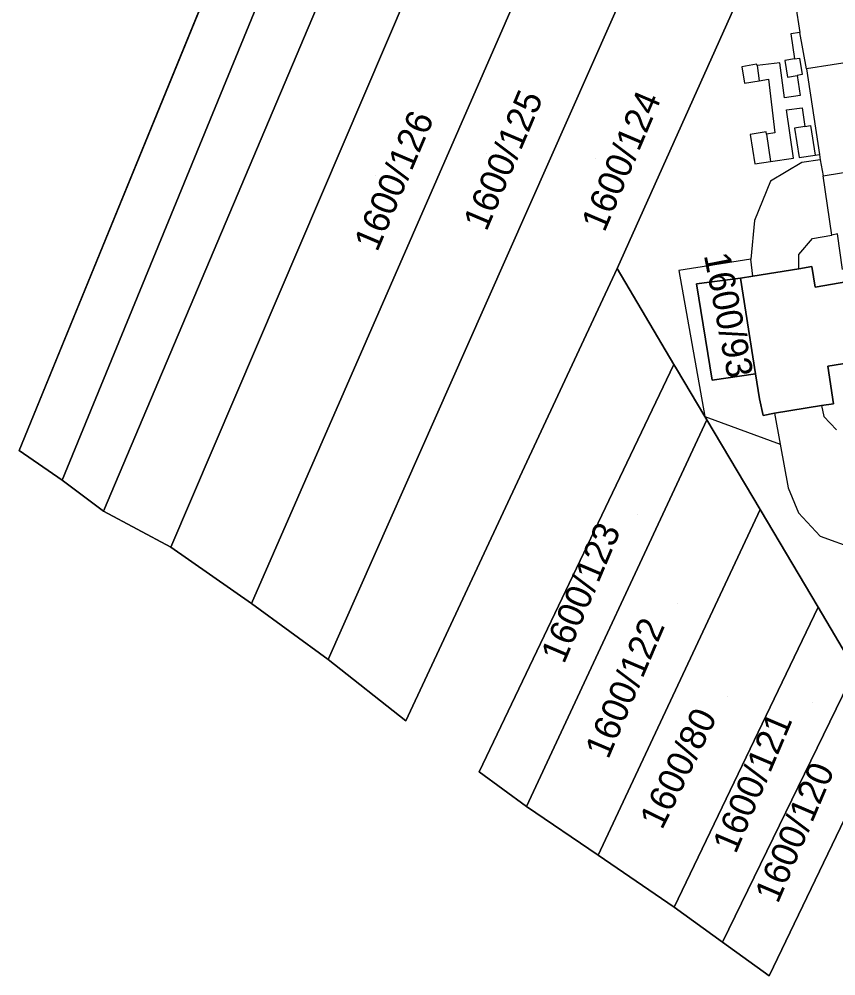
# Model space of a CAD drawing. Extents: x -262715 to -259381, y -1237238 to -1231182.
# Drawn here: x -261772.8 to -261710.5, y -1236430.9 to -1236357.8 of the extents above; entities that cross this region are included whole.
import ezdxf

# ---------------------------------------------------------------- set-up
doc = ezdxf.new("R2010")
doc.units = 0
for name, color, linetype in [('body_kn', 7, 'Continuous'), ('kladpar_druhypozemkov', 7, 'Continuous'), ('kladpar_hranice', 7, 'Continuous'), ('kladpar_parcelnecisla', 7, 'Continuous'), ('kladpar_plochy', 7, 'Continuous'), ('zappar_hrandruhpozemk', 7, 'Continuous')]:
    doc.layers.add(name, color=color, linetype=linetype)

msp = doc.modelspace()

# ---------------------------------------------------------------- linework, layer by layer
at = {"layer": 'body_kn'}
for p, q in [((-261713.93, -1236358.96), (-261713.93, -1236358.96)), ((-261713.23, -1236358.87), (-261713.23, -1236358.87)), ((-261717.68, -1236361.47), (-261717.68, -1236361.47)), ((-261716.56, -1236361.28), (-261716.56, -1236361.28)), ((-261716.51, -1236361.37), (-261716.51, -1236361.37)), ((-261716.51, -1236361.37), (-261716.51, -1236361.37)), ((-261714.76, -1236361.18), (-261714.76, -1236361.18)), ((-261714.39, -1236361), (-261714.39, -1236361)), ((-261713.64, -1236360.86), (-261713.64, -1236360.86)), ((-261713.27, -1236360.81), (-261713.27, -1236360.81)), ((-261713.45, -1236362.13), (-261713.45, -1236362.13)), ((-261713.06, -1236362.07), (-261713.06, -1236362.07)), ((-261712.74, -1236361.64), (-261712.74, -1236361.64)), ((-261712.74, -1236361.64), (-261712.74, -1236361.64)), ((-261717.47, -1236362.73), (-261717.47, -1236362.73)), ((-261716.35, -1236362.54), (-261716.35, -1236362.54)), ((-261715.64, -1236362.42), (-261715.64, -1236362.42)), ((-261714.18, -1236362.26), (-261714.18, -1236362.26)), ((-261713.21, -1236363.67), (-261713.21, -1236363.67)), ((-261714.41, -1236363.84), (-261714.41, -1236363.84)), ((-261714.27, -1236364.77), (-261714.27, -1236364.77)), ((-261713.07, -1236364.6), (-261713.07, -1236364.6)), ((-261715.82, -1236366.45), (-261715.82, -1236366.45)), ((-261715.14, -1236366.51), (-261715.14, -1236366.51)), ((-261713.64, -1236366.16), (-261713.64, -1236366.16)), ((-261712.85, -1236366.04), (-261712.85, -1236366.04)), ((-261712.85, -1236366.04), (-261712.85, -1236366.04)), ((-261712.42, -1236365.97), (-261712.42, -1236365.97)), ((-261717.04, -1236366.64), (-261717.04, -1236366.64)), ((-261715.78, -1236366.61), (-261715.78, -1236366.61)), ((-261715.78, -1236366.61), (-261715.78, -1236366.61)), ((-261715.47, -1236368.7), (-261715.47, -1236368.7)), ((-261715.47, -1236368.7), (-261715.47, -1236368.7)), ((-261713.73, -1236368.44), (-261713.73, -1236368.44)), ((-261713.29, -1236368.41), (-261713.29, -1236368.41)), ((-261713.1, -1236368.79), (-261713.1, -1236368.79)), ((-261712.07, -1236368.22), (-261712.07, -1236368.22)), ((-261711.75, -1236368.18), (-261711.75, -1236368.18)), ((-261711.68, -1236368.59), (-261711.68, -1236368.59)), ((-261711.68, -1236368.59), (-261711.68, -1236368.59)), ((-261716.69, -1236368.89), (-261716.69, -1236368.89)), ((-261715.49, -1236370.21), (-261715.49, -1236370.21)), ((-261711.45, -1236369.79), (-261711.45, -1236369.79)), ((-261711.45, -1236369.79), (-261711.45, -1236369.79)), ((-261716.7, -1236373.22), (-261716.7, -1236373.22)), ((-261712.28, -1236374.58), (-261712.28, -1236374.58)), ((-261710.81, -1236374.33), (-261710.81, -1236374.33)), ((-261710.81, -1236374.33), (-261710.81, -1236374.33)), ((-261713.32, -1236375.81), (-261713.32, -1236375.81)), ((-261716.98, -1236376.17), (-261716.98, -1236376.17)), ((-261716.98, -1236376.17), (-261716.98, -1236376.17)), ((-261712.32, -1236376.72), (-261712.32, -1236376.72)), ((-261727.2, -1236376.88), (-261727.2, -1236376.88)), ((-261727.2, -1236376.88), (-261727.2, -1236376.88)), ((-261722.49, -1236377.03), (-261722.49, -1236377.03)), ((-261716.84, -1236377.47), (-261716.84, -1236377.47)), ((-261716.84, -1236377.47), (-261716.84, -1236377.47)), ((-261713.33, -1236376.89), (-261713.33, -1236376.89)), ((-261713.33, -1236376.89), (-261713.33, -1236376.89)), ((-261721.13, -1236378.05), (-261721.13, -1236378.05)), ((-261717.77, -1236377.6), (-261717.77, -1236377.6)), ((-261717.77, -1236377.6), (-261717.77, -1236377.6)), ((-261712.07, -1236378.3), (-261712.07, -1236378.3)), ((-261738.7, -1236382.89), (-261738.7, -1236382.89)), ((-261722.86, -1236384.19), (-261722.86, -1236384.19)), ((-261722.86, -1236384.19), (-261722.86, -1236384.19)), ((-261722.66, -1236384.52), (-261722.66, -1236384.52)), ((-261711.11, -1236384.33), (-261711.11, -1236384.33)), ((-261719.93, -1236385.39), (-261719.93, -1236385.39)), ((-261716.63, -1236384.9), (-261716.63, -1236384.9)), ((-261716.31, -1236386.81), (-261716.31, -1236386.81)), ((-261711.58, -1236387.34), (-261711.58, -1236387.34)), ((-261711.58, -1236387.34), (-261711.58, -1236387.34)), ((-261710.66, -1236387.19), (-261710.66, -1236387.19)), ((-261720.49, -1236388.17), (-261720.49, -1236388.17)), ((-261720.49, -1236388.17), (-261720.49, -1236388.17)), ((-261720.34, -1236388.42), (-261720.34, -1236388.42)), ((-261720.34, -1236388.42), (-261720.34, -1236388.42)), ((-261716.03, -1236388.08), (-261716.03, -1236388.08)), ((-261715.17, -1236387.91), (-261715.17, -1236387.91)), ((-261715.17, -1236387.91), (-261715.17, -1236387.91)), ((-261711.41, -1236388.18), (-261711.41, -1236388.18)), ((-261714.75, -1236390.29), (-261714.75, -1236390.29)), ((-261772.85, -1236390.76), (-261772.85, -1236390.76)), ((-261772.85, -1236390.76), (-261772.85, -1236390.76)), ((-261769.56, -1236393.02), (-261769.56, -1236393.02)), ((-261714.13, -1236393.6), (-261714.13, -1236393.6)), ((-261766.42, -1236395.39), (-261766.42, -1236395.39)), ((-261766.42, -1236395.39), (-261766.42, -1236395.39)), ((-261716.28, -1236395.26), (-261716.28, -1236395.26)), ((-261713.34, -1236395.53), (-261713.34, -1236395.53)), ((-261711.68, -1236397.29), (-261711.68, -1236397.29)), ((-261761.26, -1236398.13), (-261761.26, -1236398.13)), ((-261755.1, -1236402.44), (-261755.1, -1236402.44)), ((-261755.1, -1236402.44), (-261755.1, -1236402.44)), ((-261711.85, -1236402.73), (-261711.85, -1236402.73)), ((-261749.26, -1236406.71), (-261749.26, -1236406.71)), ((-261749.26, -1236406.71), (-261749.26, -1236406.71)), ((-261743.32, -1236411.39), (-261743.32, -1236411.39)), ((-261737.72, -1236415.3), (-261737.72, -1236415.3)), ((-261734.11, -1236417.94), (-261734.11, -1236417.94)), ((-261734.11, -1236417.94), (-261734.11, -1236417.94)), ((-261728.63, -1236421.65), (-261728.63, -1236421.65)), ((-261728.63, -1236421.65), (-261728.63, -1236421.65)), ((-261722.83, -1236425.61), (-261722.83, -1236425.61)), ((-261722.83, -1236425.61), (-261722.83, -1236425.61)), ((-261719.14, -1236428.29), (-261719.14, -1236428.29)), ((-261719.14, -1236428.29), (-261719.14, -1236428.29)), ((-261715.58, -1236430.86), (-261715.58, -1236430.86))]:
    msp.add_line(p, q, dxfattribs=at)
at = {"layer": 'kladpar_druhypozemkov'}
for p, q in [((-261737.17, -1236368.07), (-261737.17, -1236368.07)), ((-261728.81, -1236368.44), (-261728.81, -1236368.44)), ((-261745.66, -1236369.81), (-261745.66, -1236369.81)), ((-261717.79, -1236381.32), (-261717.79, -1236381.32)), ((-261725.64, -1236395.68), (-261725.64, -1236395.68)), ((-261722.61, -1236402.46), (-261722.61, -1236402.46)), ((-261718.76, -1236409.5), (-261718.76, -1236409.5)), ((-261712.31, -1236409.99), (-261712.31, -1236409.99))]:
    msp.add_line(p, q, dxfattribs=at)
at = {"layer": 'kladpar_hranice'}
for p, q in [((-261772.85, -1236390.76), (-261729.67, -1236285.32)), ((-261727.2, -1236376.88), (-261722.86, -1236384.19)), ((-261720.34, -1236388.42), (-261734.11, -1236417.94)), ((-261709.01, -1236407.5), (-261719.14, -1236428.29)), ((-261722.83, -1236425.61), (-261728.63, -1236421.65)), ((-261719.14, -1236428.29), (-261722.83, -1236425.61))]:
    msp.add_line(p, q, dxfattribs=at)
for points in [[(-261729.67, -1236285.32), (-261772.85, -1236390.76), (-261769.56, -1236393.02), (-261766.42, -1236395.39), (-261761.26, -1236398.13), (-261755.1, -1236402.44), (-261749.26, -1236406.71), (-261743.32, -1236411.39), (-261727.2, -1236376.88)], [(-261727.16, -1236289.77), (-261769.56, -1236393.02), (-261772.85, -1236390.76)], [(-261724.03, -1236295.33), (-261766.42, -1236395.39), (-261769.56, -1236393.02), (-261727.16, -1236289.77)], [(-261766.42, -1236395.39), (-261724.03, -1236295.33), (-261723.21, -1236296.78), (-261720.21, -1236302.16), (-261761.26, -1236398.13), (-261766.42, -1236395.39)], [(-261755.1, -1236402.44), (-261761.26, -1236398.13), (-261720.21, -1236302.16)], [(-261715.3, -1236310.95), (-261728.67, -1236341.94), (-261755.1, -1236402.44)], [(-261749.26, -1236406.71), (-261755.1, -1236402.44), (-261728.67, -1236341.94), (-261715.3, -1236310.95)], [(-261710.55, -1236319.47), (-261719.76, -1236340.21), (-261738.7, -1236382.89), (-261749.26, -1236406.71)], [(-261727.2, -1236376.88), (-261743.32, -1236411.39), (-261749.26, -1236406.71), (-261738.7, -1236382.89), (-261719.76, -1236340.21), (-261710.55, -1236319.47)], [(-261710.55, -1236319.47), (-261705.52, -1236328.61), (-261727.2, -1236376.88)], [(-261727.2, -1236376.88), (-261705.52, -1236328.61)], [(-261689.71, -1236357.2), (-261686.06, -1236363.77), (-261681.32, -1236372.31), (-261680.07, -1236374.57), (-261674.77, -1236384.12), (-261676.54, -1236387.86), (-261678.39, -1236391.77), (-261678.71, -1236392.44), (-261688.12, -1236412.33), (-261689.12, -1236412.13), (-261693.35, -1236411.27), (-261697.7, -1236410.38), (-261705.02, -1236408.89), (-261708.62, -1236408.16), (-261709.01, -1236407.5), (-261711.85, -1236402.73), (-261716.28, -1236395.26), (-261720.34, -1236388.42), (-261720.49, -1236388.17), (-261722.66, -1236384.52)], [(-261716.84, -1236377.47), (-261717.77, -1236377.6), (-261721.13, -1236378.05), (-261719.93, -1236385.39), (-261716.63, -1236384.9), (-261716.31, -1236386.81), (-261716.03, -1236388.08), (-261715.17, -1236387.91), (-261711.58, -1236387.34), (-261710.66, -1236387.19), (-261711.11, -1236384.33), (-261708.87, -1236383.97), (-261708.15, -1236388.1), (-261689.76, -1236385.07), (-261691.37, -1236374.95), (-261709.58, -1236377.86), (-261712.07, -1236378.3), (-261712.32, -1236376.72), (-261713.33, -1236376.89), (-261716.84, -1236377.47)], [(-261716.84, -1236377.47), (-261713.33, -1236376.89), (-261712.32, -1236376.72), (-261712.07, -1236378.3), (-261709.58, -1236377.86), (-261691.37, -1236374.95), (-261689.76, -1236385.07), (-261708.15, -1236388.1), (-261708.87, -1236383.97), (-261711.11, -1236384.33), (-261710.66, -1236387.19), (-261711.58, -1236387.34), (-261715.17, -1236387.91), (-261716.03, -1236388.08), (-261716.31, -1236386.81), (-261716.63, -1236384.9), (-261717.77, -1236377.6), (-261716.84, -1236377.47)], [(-261722.66, -1236384.52), (-261722.86, -1236384.19), (-261727.2, -1236376.88)], [(-261717.77, -1236377.6), (-261716.63, -1236384.9), (-261719.93, -1236385.39), (-261721.13, -1236378.05), (-261717.77, -1236377.6)], [(-261734.11, -1236417.94), (-261737.72, -1236415.3), (-261722.86, -1236384.19)], [(-261722.86, -1236384.19), (-261737.72, -1236415.3), (-261734.11, -1236417.94), (-261728.63, -1236421.65), (-261722.83, -1236425.61), (-261719.14, -1236428.29), (-261715.58, -1236430.86), (-261705.02, -1236408.89)], [(-261722.86, -1236384.19), (-261722.66, -1236384.52), (-261720.49, -1236388.17), (-261720.34, -1236388.42)], [(-261728.63, -1236421.65), (-261734.11, -1236417.94), (-261720.34, -1236388.42)], [(-261720.34, -1236388.42), (-261716.28, -1236395.26), (-261728.63, -1236421.65)], [(-261728.63, -1236421.65), (-261716.28, -1236395.26), (-261711.85, -1236402.73), (-261722.83, -1236425.61)], [(-261722.83, -1236425.61), (-261711.85, -1236402.73), (-261709.01, -1236407.5)], [(-261705.02, -1236408.89), (-261715.58, -1236430.86), (-261719.14, -1236428.29), (-261709.01, -1236407.5)]]:
    msp.add_lwpolyline(points, dxfattribs=at)
at = {"layer": 'kladpar_plochy'}
for p, q in [((-261729.67, -1236285.32), (-261772.85, -1236390.76)), ((-261727.2, -1236376.88), (-261705.52, -1236328.61)), ((-261712.32, -1236376.72), (-261713.33, -1236376.89)), ((-261712.07, -1236378.3), (-261712.32, -1236376.72)), ((-261743.32, -1236411.39), (-261727.2, -1236376.88)), ((-261722.86, -1236384.19), (-261727.2, -1236376.88)), ((-261727.2, -1236376.88), (-261722.86, -1236384.19)), ((-261716.84, -1236377.47), (-261717.77, -1236377.6)), ((-261713.33, -1236376.89), (-261716.84, -1236377.47)), ((-261717.77, -1236377.6), (-261721.13, -1236378.05)), ((-261721.13, -1236378.05), (-261719.93, -1236385.39)), ((-261709.58, -1236377.86), (-261712.07, -1236378.3)), ((-261711.11, -1236384.33), (-261708.87, -1236383.97)), ((-261722.86, -1236384.19), (-261737.72, -1236415.3)), ((-261722.66, -1236384.52), (-261722.86, -1236384.19)), ((-261720.49, -1236388.17), (-261722.66, -1236384.52)), ((-261710.66, -1236387.19), (-261711.11, -1236384.33)), ((-261719.93, -1236385.39), (-261716.63, -1236384.9)), ((-261716.63, -1236384.9), (-261716.31, -1236386.81)), ((-261716.31, -1236386.81), (-261716.03, -1236388.08)), ((-261715.17, -1236387.91), (-261711.58, -1236387.34)), ((-261711.58, -1236387.34), (-261710.66, -1236387.19)), ((-261720.34, -1236388.42), (-261720.49, -1236388.17)), ((-261716.28, -1236395.26), (-261720.34, -1236388.42)), ((-261716.03, -1236388.08), (-261715.17, -1236387.91)), ((-261772.85, -1236390.76), (-261769.56, -1236393.02)), ((-261769.56, -1236393.02), (-261766.42, -1236395.39)), ((-261766.42, -1236395.39), (-261761.26, -1236398.13)), ((-261711.85, -1236402.73), (-261716.28, -1236395.26)), ((-261761.26, -1236398.13), (-261755.1, -1236402.44)), ((-261755.1, -1236402.44), (-261749.26, -1236406.71)), ((-261709.01, -1236407.5), (-261711.85, -1236402.73)), ((-261749.26, -1236406.71), (-261743.32, -1236411.39)), ((-261715.58, -1236430.86), (-261705.02, -1236408.89)), ((-261737.72, -1236415.3), (-261734.11, -1236417.94)), ((-261734.11, -1236417.94), (-261728.63, -1236421.65)), ((-261728.63, -1236421.65), (-261722.83, -1236425.61)), ((-261722.83, -1236425.61), (-261719.14, -1236428.29)), ((-261719.14, -1236428.29), (-261715.58, -1236430.86))]:
    msp.add_line(p, q, dxfattribs=at)
for points in [[(-261727.16, -1236289.77), (-261769.56, -1236393.02), (-261772.85, -1236390.76), (-261729.67, -1236285.32)], [(-261727.16, -1236289.77), (-261724.03, -1236295.33), (-261766.42, -1236395.39), (-261769.56, -1236393.02)], [(-261766.42, -1236395.39), (-261724.03, -1236295.33), (-261723.21, -1236296.78), (-261720.21, -1236302.16), (-261761.26, -1236398.13)], [(-261720.21, -1236302.16), (-261715.3, -1236310.95), (-261728.67, -1236341.94), (-261755.1, -1236402.44), (-261761.26, -1236398.13)], [(-261715.3, -1236310.95), (-261710.72, -1236319.17), (-261710.55, -1236319.47), (-261719.76, -1236340.21), (-261738.7, -1236382.89), (-261749.26, -1236406.71), (-261755.1, -1236402.44), (-261728.67, -1236341.94)], [(-261727.2, -1236376.88), (-261743.32, -1236411.39), (-261749.26, -1236406.71), (-261738.7, -1236382.89), (-261719.76, -1236340.21), (-261710.55, -1236319.47), (-261705.52, -1236328.61)], [(-261716.84, -1236377.47), (-261713.33, -1236376.89), (-261712.32, -1236376.72), (-261712.07, -1236378.3), (-261709.58, -1236377.86), (-261691.37, -1236374.95), (-261689.76, -1236385.07), (-261708.15, -1236388.1), (-261708.87, -1236383.97), (-261711.11, -1236384.33), (-261710.66, -1236387.19), (-261711.58, -1236387.34), (-261715.17, -1236387.91), (-261716.03, -1236388.08), (-261716.31, -1236386.81), (-261716.63, -1236384.9), (-261717.77, -1236377.6)], [(-261717.77, -1236377.6), (-261716.63, -1236384.9), (-261719.93, -1236385.39), (-261721.13, -1236378.05)], [(-261720.34, -1236388.42), (-261734.11, -1236417.94), (-261737.72, -1236415.3), (-261722.86, -1236384.19), (-261722.66, -1236384.52), (-261720.49, -1236388.17)], [(-261720.34, -1236388.42), (-261716.28, -1236395.26), (-261728.63, -1236421.65), (-261734.11, -1236417.94)], [(-261722.83, -1236425.61), (-261728.63, -1236421.65), (-261716.28, -1236395.26), (-261711.85, -1236402.73)], [(-261709.01, -1236407.5), (-261719.14, -1236428.29), (-261722.83, -1236425.61), (-261711.85, -1236402.73)], [(-261705.02, -1236408.89), (-261715.58, -1236430.86), (-261719.14, -1236428.29), (-261709.01, -1236407.5), (-261708.62, -1236408.16)]]:
    msp.add_lwpolyline(points, close=True, dxfattribs=at)
at = {"layer": 'zappar_hrandruhpozemk'}
for p, q in [((-261691.84, -1236358.3), (-261712.74, -1236361.64)), ((-261713.93, -1236358.96), (-261713.64, -1236360.86)), ((-261712.74, -1236361.64), (-261713.23, -1236358.87)), ((-261716.56, -1236361.28), (-261717.68, -1236361.47)), ((-261716.51, -1236361.37), (-261716.56, -1236361.28)), ((-261714.41, -1236363.84), (-261714.76, -1236361.18)), ((-261713.64, -1236360.86), (-261713.27, -1236360.81)), ((-261713.27, -1236360.81), (-261713.06, -1236362.07)), ((-261713.06, -1236362.07), (-261713.45, -1236362.13)), ((-261712.74, -1236361.64), (-261711.75, -1236368.18)), ((-261715.64, -1236362.42), (-261715.14, -1236366.51)), ((-261715.14, -1236366.51), (-261715.78, -1236366.61)), ((-261712.85, -1236366.04), (-261712.42, -1236365.97)), ((-261712.42, -1236365.97), (-261712.07, -1236368.22)), ((-261711.45, -1236369.79), (-261690.64, -1236366.42)), ((-261717.04, -1236366.64), (-261716.69, -1236368.89)), ((-261715.78, -1236366.61), (-261715.47, -1236368.7)), ((-261716.69, -1236368.89), (-261715.47, -1236368.7)), ((-261715.47, -1236368.7), (-261713.73, -1236368.44)), ((-261711.68, -1236368.59), (-261711.45, -1236369.79)), ((-261715.49, -1236370.21), (-261716.7, -1236373.22)), ((-261710.81, -1236374.33), (-261711.45, -1236369.79)), ((-261716.7, -1236373.22), (-261716.98, -1236376.17)), ((-261716.98, -1236376.17), (-261722.49, -1236377.03)), ((-261716.84, -1236377.47), (-261716.98, -1236376.17)), ((-261722.49, -1236377.03), (-261720.49, -1236388.17)), ((-261711.58, -1236387.34), (-261711.41, -1236388.18)), ((-261715.17, -1236387.91), (-261714.75, -1236390.29)), ((-261711.41, -1236388.18), (-261710.43, -1236389.18)), ((-261714.13, -1236393.6), (-261713.34, -1236395.53))]:
    msp.add_line(p, q, dxfattribs=at)
for points in [[(-261713.57, -1236356.72), (-261713.23, -1236358.87), (-261713.93, -1236358.96)], [(-261717.68, -1236361.47), (-261717.47, -1236362.73), (-261716.35, -1236362.54)], [(-261714.76, -1236361.18), (-261716.51, -1236361.37), (-261716.35, -1236362.54), (-261715.64, -1236362.42)], [(-261713.64, -1236360.86), (-261714.39, -1236361), (-261714.18, -1236362.26), (-261713.45, -1236362.13), (-261713.21, -1236363.67), (-261714.41, -1236363.84)], [(-261713.73, -1236368.44), (-261714.27, -1236364.77), (-261713.07, -1236364.6), (-261712.85, -1236366.04), (-261713.64, -1236366.16), (-261713.29, -1236368.41), (-261712.07, -1236368.22), (-261711.75, -1236368.18), (-261711.68, -1236368.59), (-261713.1, -1236368.79), (-261715.49, -1236370.21)], [(-261715.78, -1236366.61), (-261715.82, -1236366.45), (-261717.04, -1236366.64)], [(-261713.33, -1236376.89), (-261713.32, -1236375.81), (-261712.28, -1236374.58), (-261710.81, -1236374.33)], [(-261709.99, -1236376.96), (-261710.37, -1236374.23), (-261710.81, -1236374.33)], [(-261720.49, -1236388.17), (-261714.75, -1236390.29), (-261714.13, -1236393.6)], [(-261713.34, -1236395.53), (-261711.68, -1236397.29), (-261709.02, -1236398.26), (-261705.24, -1236398.04), (-261688.57, -1236392.47)]]:
    msp.add_lwpolyline(points, dxfattribs=at)

# ---------------------------------------------------------------- texts
at = {"layer": 'kladpar_parcelnecisla'}
for s, rotation, p in [('1600/125', 67, (-261737.168, -1236374.103)), ('1600/124', 67, (-261728.157, -1236374.172)), ('1600/126', 67, (-261745.507, -1236375.672)), ('1600/93', 281, (-261720.575, -1236375.854)), ('1600/123', 67, (-261731.247, -1236407.116)), ('1600/122', 67, (-261727.871, -1236414.392)), ('1600/80', 64, (-261723.758, -1236419.781)), ('1600/121', 67, (-261718.137, -1236421.615)), ('1600/120', 67, (-261714.919, -1236425.411))]:
    msp.add_text(s, height=2, rotation=rotation, dxfattribs=at).set_placement(p)

doc.saveas('drawing.dxf')
